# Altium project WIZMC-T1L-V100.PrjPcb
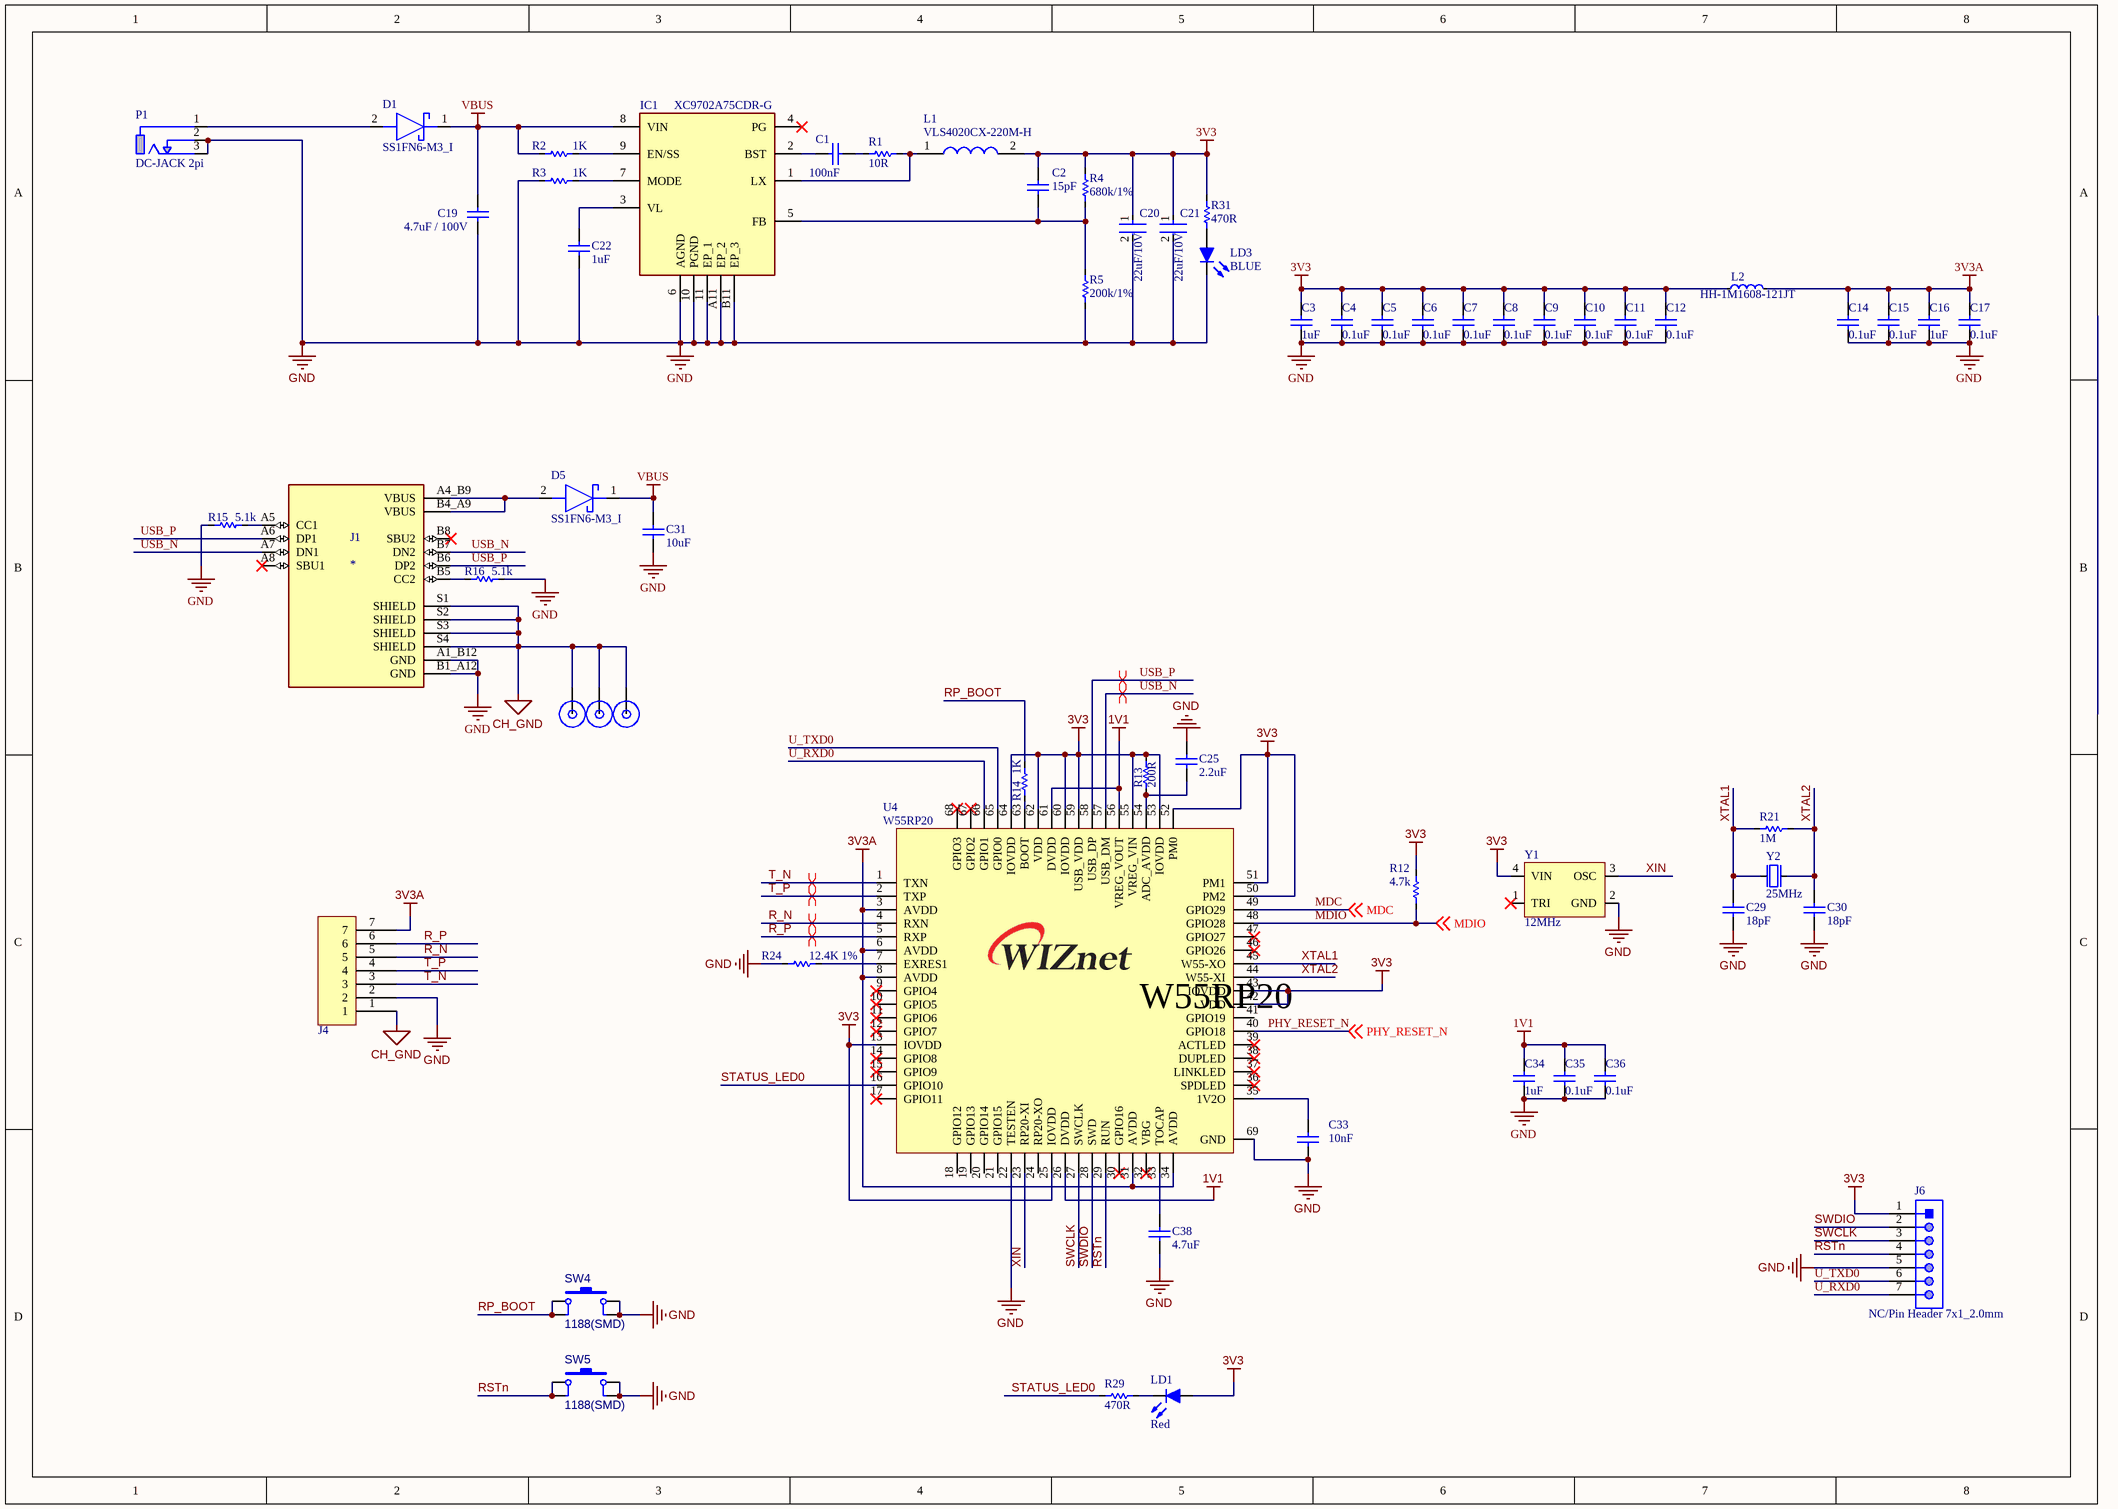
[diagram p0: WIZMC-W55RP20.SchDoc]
3 sheets, 133 parts. Net scope: flat (ports and power ports of the same name join across sheets).
Board file: WIZMC-T1L-V100.PcbDoc
Sheets:
  WIZMC-W55RP20.SchDoc
  WIZMC-ADIN1100.SchDoc
  WIZMC-ADIN1200.SchDoc

## Sheet WIZMC-W55RP20.SchDoc
size A3; SheetNumber: 1; SheetTotal: 3

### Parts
C1  100nF  [CAP-0402]
C2  15pF  [CAP-0402]
C3  1uF  [CAP-0402]
C4  0.1uF  [CAP-0402]
C5  0.1uF  [CAP-0402]
C6  0.1uF  [CAP-0402]
C7  0.1uF  [CAP-0402]
C8  0.1uF  [CAP-0402]
C9  0.1uF  [CAP-0402]
C10  0.1uF  [CAP-0402]
C11  0.1uF  [CAP-0402]
C12  0.1uF  [CAP-0402]
C14  0.1uF  [CAP-0402]
C15  0.1uF  [CAP-0402]
C16  1uF  [CAP-0402]
C17  0.1uF  [CAP-0402]
C19  4.7uF / 100V  [CAP-1210]
C20  22uF/10V  [CAP-1206]
C21  22uF/10V  [CAP-1206]
C22  1uF  [CAP-0603]
C25  2.2uF  [CAP-0603]
C29  18pF  [CAP-0402]
C30  18pF  [CAP-0402]
C31  10uF  [CAP-0805]
C33  10nF  [CAP-0402]
C34  1uF  [CAP-0402]
C35  0.1uF  [CAP-0402]
C36  0.1uF  [CAP-0402]
C38  4.7uF  [CAP-0603]
D1  SS1FN6-M3_I  [SODFL3718X108N]
D5  SS1FN6-M3_I  [SODFL3718X108N]
H1  PCB Hole  [M3_HOLE]  (value not drawn)  (no BOM)
H2  PCB Hole  [M3_HOLE]  (value not drawn)  (no BOM)
H4  PCB Hole  [M3_HOLE]  (value not drawn)  (no BOM)
IC1  XC9702A75CDR-G  [XC9135B18CDRG]
J1  *  [USB-C]
J4  2.54mm 1x9 Pin Header DIP  [Pin-Header(DIP)_7x1_2.0mm]  (value not drawn)
J6  NC/Pin Header 7x1_2.0mm  [Pin-Header(DIP)_7x1_2.0mm]
L1  VLS4020CX-220M-H  [XAL40XX]
L2  HH-1M1608-121JT  [IND-0603]
LD1  Red  [LED-0603-RED]
LD3  BLUE  [LED-0603-RED]
P1  DC-JACK 2pi  [DC-JACK 2pi]
R1  10R  [RES-0402]
R2  1K  [RES-0402]
R3  1K  [RES-0402]
R4  680k/1%  [RES-0402]
R5  200k/1%  [RES-0402]
R12  4.7k  [RES-0402]
R13  200R  [RES-0402]
R14  1K  [RES-0402]
R15  5.1k  [RES-0402]
R16  5.1k  [RES-0402]
R21  1M  [RES-0402]
R24  12.4K 1%  [RES-0402]
R29  470R  [RES-0402]
R31  470R  [RES-0402]
SW4  1188(SMD)  [1188]
SW5  1188(SMD)  [1188]
U4  W55RP20  [QFN68]
Y1  12MHz  [3225_XTAL]
Y2  25MHz  [OSC-82J0626]

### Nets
1V1: C34.2 C35.2 C36.2 U4.26(DVDD) U4.56(VREG_VOUT) U4.61(DVDD)
3V3: C2.2 C3.2 C4.2 C5.2 C6.2 C7.2 C8.2 C9.2 C10.2 C11.2 C12.2 C20.1 C21.1 J6.1 L1.2 L2.1 LD1.1(A) R4.2 R12.2 R13.2 R31.1 U4.13(IOVDD) U4.25(IOVDD) U4.42(VDD) U4.43(IOVDD) U4.50(PM2) U4.51(PM1) U4.52(PM0) U4.53(IOVDD) U4.55(VREG_VIN) U4.59(USB_VDD) U4.60(IOVDD) U4.62(VDD) U4.64(IOVDD) Y1.4(VIN)
3V3A: C14.2 C15.2 C16.2 C17.2 J4.7 L2.2 U4.3(AVDD) U4.6(AVDD) U4.8(AVDD) U4.31(AVDD) U4.34(AVDD)
CH_GND: H1.1 H2.1 H4.1 J1.S1(SHIELD) J1.S2(SHIELD) J1.S3(SHIELD) J1.S4(SHIELD) J4.1
GND: C3.1 C4.1 C5.1 C6.1 C7.1 C8.1 C9.1 C10.1 C11.1 C12.1 C14.1 C15.1 C16.1 C17.1 C19.1 C20.2 C21.2 C22.1 C25.1 C29.1 C30.1 C31.1 C33.1 C34.1 C35.1 C36.1 C38.1 IC1.6(AGND) IC1.10(PGND) IC1.11(EP_1) IC1.A11(EP_2) IC1.B11(EP_3) J1.A1_B12(GND) J1.B1_A12(GND) J4.2 J6.5 LD3.2(K) P1.2(GND) P1.3(GND) R3.1 R5.1 R15.2 R16.1 R24.1 SW4.1 SW4.2 SW5.1 SW5.2 U4.22(TESTEN) U4.69(GND) Y1.2(GND) Y2.2(GND) Y2.4(GND)
VBUS: C19.2 C31.2 D1.1(K) D5.1(K) IC1.8(VIN) R2.1
MDC: U4.49(GPIO29) ; off-sheet MDC
MDIO: R12.1 U4.48(GPIO28) ; off-sheet MDIO
PHY_RESET_N: U4.40(GPIO18) ; off-sheet PHY_RESET_N
R_N: J4.5 U4.4(RXN)
R_P: J4.6 U4.5(RXP)
RP_BOOT: R14.2 SW4.3 SW4.4
RSTn: J6.4 SW5.3 SW5.4 U4.29(RUN)
STATUS_LED0: R29.1 U4.16(GPIO10)
SWCLK: J6.3 U4.27(SWCLK)
SWDIO: J6.2 U4.28(SWD)
T_N: J4.3 U4.1(TXN)
T_P: J4.4 U4.2(TXP)
U_RXD0: J6.7 U4.66(GPIO1)
U_TXD0: J6.6 U4.65(GPIO0)
USB_N: J1.A7(DN1) J1.B7(DN2) U4.57(USB_DM)
USB_P: J1.A6(DP1) J1.B6(DP2) U4.58(USB_DP)
XIN: U4.23(RP20-XI) Y1.3(OSC)
XTAL1: C29.2 R21.1 U4.45(W55-XO) Y2.1(inp)
XTAL2: C30.2 R21.2 U4.44(W55-XI) Y2.3(out)
NetC1_1: C1.1 R1.1
NetC1_2: C1.2 IC1.2(BST)
NetC2_1: C2.1 IC1.5(FB) R4.1 R5.2
NetC22_2: C22.2 IC1.3(VL)
NetC25_2: C25.2 R13.1 U4.54(ADC_AVDD)
NetC33_2: C33.2 U4.35(1V2O)
NetC38_2: C38.2 U4.33(TOCAP)
NetD1_2: D1.2(A) P1.1(VCC)
NetD5_2: D5.2(A) J1.A4_B9(VBUS) J1.B4_A9(VBUS)
NetIC1_1: IC1.1(LX) L1.1 R1.2
NetIC1_7: IC1.7(MODE) R3.2
NetIC1_9: IC1.9(EN/SS) R2.2
NetJ1_A5: J1.A5(CC1) R15.1
NetJ1_B5: J1.B5(CC2) R16.2
NetLD1_2: LD1.2(K) R29.2
NetLD3_1: LD3.1(A) R31.2
NetR14_1: R14.1 U4.63(BOOT)
NetR24_2: R24.2 U4.7(EXRES1)

Not connected (* = marked no-connect by the designer): IC1 4(PG)*; J1 A8(SBU1)* B8(SBU2)*; U4 9(GPIO4)* 10(GPIO5)* 11(GPIO6)* 12(GPIO7)* 14(GPIO8)* 15(GPIO9)* 17(GPIO11)* 18(GPIO12) 19(GPIO13) 20(GPIO14) 21(GPIO15) 24(RP20-XO) 30(GPIO16)* 32(VBG)* 36(SPDLED)* 37(LINKLED)* 38(DUPLED)* 39(ACTLED)* 41(GPIO19) 46(GPIO26)* 47(GPIO27)* 67(GPIO2)* 68(GPIO3)*; Y1 1(TRI)*

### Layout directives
differential pair: R_N, R_P, T_N, T_P, USB_N, USB_P

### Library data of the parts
C1 C2 C25 C29 C30 C33 = CAP-0402: MLCC-0402(1005)
C3-C12 C14-C17 C34-C36 = CAP-0402: Ceramic CAP 0402(1005)
C19 = CAP-1210: MLCC-1210(3225)
C20 C21 = CAP-1206: MLCC-1206(3216); Manufacturer: KEMET; Manufacturer Part Number: C1206X102KGRACTU; Tolerance: 10%; Voltage Rating (DC): 2kV; Capacitance: 1nF; Dielectric: X7R; Dielectric Material: Ceramic
C22 C38 = CAP-0603: MLCC-0603(1608)
C31 = CAP-0805: MLCC-0805(2012)
D1 D5 = SS1FN6-M3_I: Schottky Diode; Manufacturer_Name: Vishay; Manufacturer_Part_Number: SS1FN6-M3/I
H1 H2 H4 = PCB Hole: PCB Supporter Hole
IC1 = XC9702A75CDR-G: Integrated Circuit; Manufacturer_Name: Torex
J1 = TYPE-C-31-M-12: USB Connectors 24 Receptacle 1 8.94*7.3mm RoHS; MF: HRO Electronics Co., Ltd.
J4 = 2.54mm 1x7 Pin Header
J6 = Pin Header 7x1_2.0mm: Connector; Manufacturer_Name: Harwin; Manufacturer_Part_Number: M22-2010705
L1 = XAL4040-822MEC: Inductor; Manufacturer_Name: COILCRAFT
L2 = IND-0603: Inductor 0603(1608)
LD1 LD3 = LED-0603
R1-R5 R12-R14 R21 R24 = RES-0402: Chip Resistor 0402(1005)
R15 R16 R29 R31 = RES-0402
SW4 SW5 = 1188(SMD): SMD TACT SWITCH
U4 = W55RP20: WIZnet Hardwired TCP/IP Chip
Y1 = OSC-3225: OSC 25MHz,3.2x2.5 SMD
Y2 = OSC-82J0626-25MHz: X-tal 25MHz,3.2x2.5 SMD, CL=18pF

## Sheet WIZMC-ADIN1100.SchDoc: WIZMD-SPE
size A4; Date: 2025-08-18; DocumentNumber: 2; Revision: 0.1; SheetNumber: 2; SheetTotal: 3
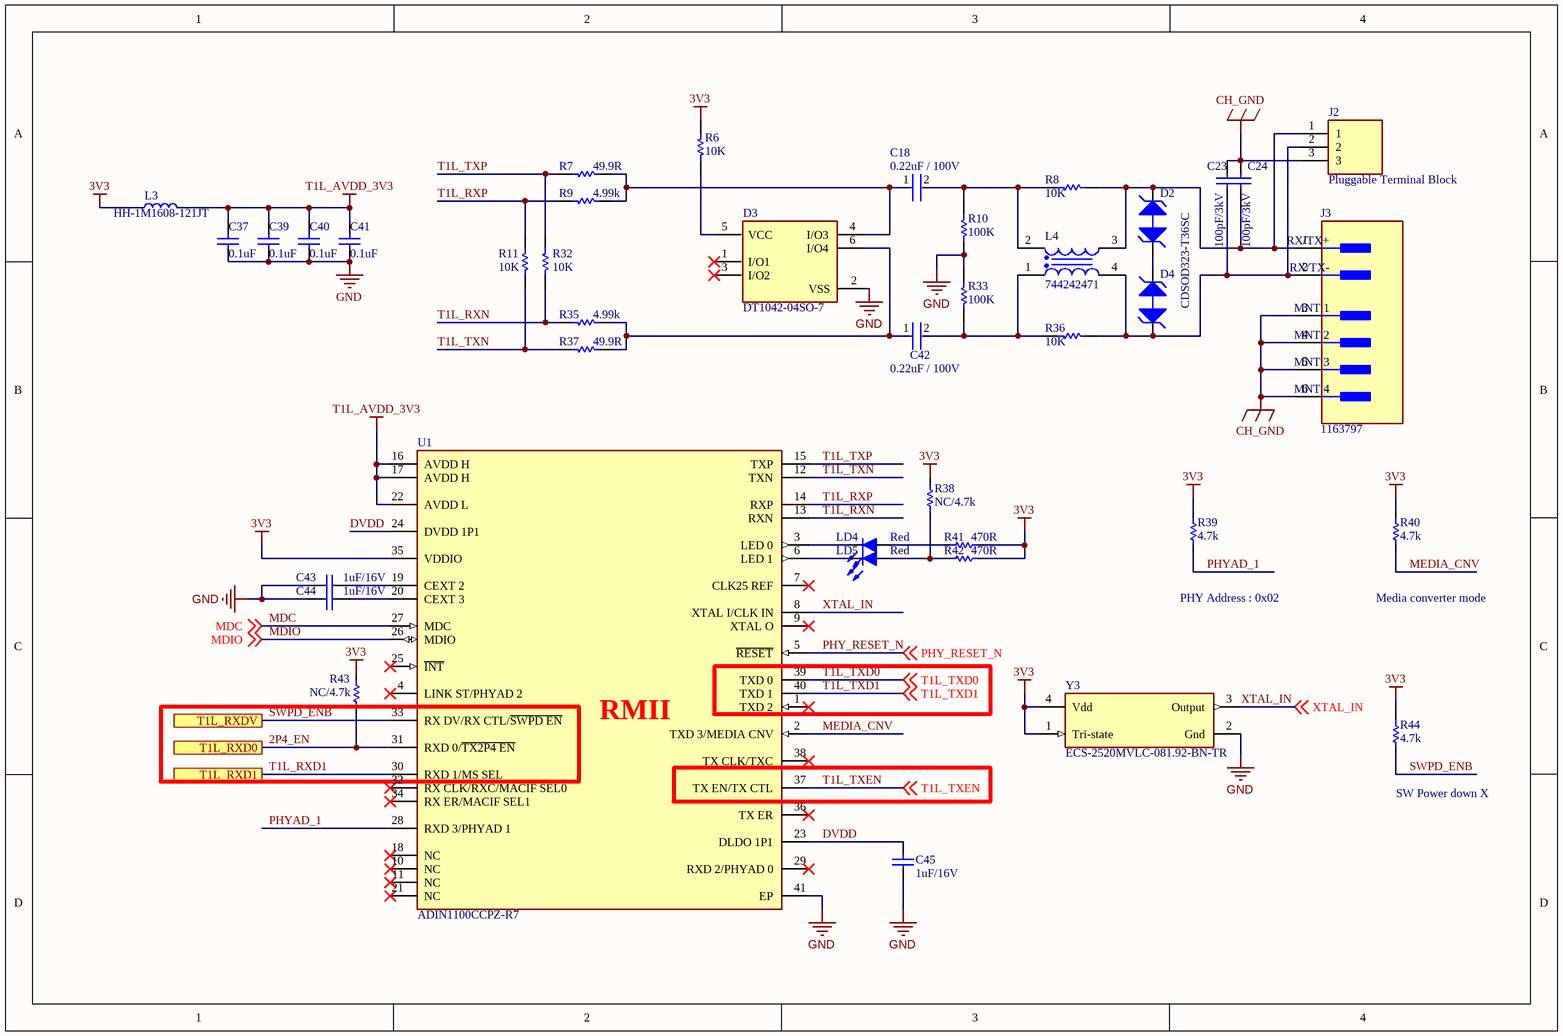
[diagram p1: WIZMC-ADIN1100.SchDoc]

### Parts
C18  0.22uF / 100V  [CAP-1206]
C23  100pF/3kV  [CAP-1808]
C24  100pF/3kV  [CAP-1808]
C37  0.1uF  [CAP-0402]
C39  0.1uF  [CAP-0402]
C40  0.1uF  [CAP-0402]
C41  0.1uF  [CAP-0402]
C42  0.22uF / 100V  [CAP-1206]
C43  1uF/16V  [CAP-0603]
C44  1uF/16V  [CAP-0603]
C45  1uF/16V  [CAP-0603]
D2  CDSOD323-T36SC  [SOD-323(1-C,2-A)]  (value not drawn)
D3  DT1042-04SO-7  [FP-SOT26_SC74R-MFG]
D4  CDSOD323-T36SC  [SOD-323(1-C,2-A)]
J2  Pluggable Terminal Block  [1803280]
J3  1163797  [FP-1163797-MFG]
L3  HH-1M1608-121JT  [IND-0603]
L4  744242471  [WE-SLM_L6W3.3H3.3]
LD4  Red  [LED-0603-RED]
LD5  Red  [LED-0603-RED]
R6  10K  [RES-0603]
R7  49.9R  [RES-0603]
R8  10K  [RES-0603]
R9  4.99k  [RES-0603]
R10  100K  [RES-0603]
R11  10K  [RES-0603]
R32  10K  [RES-0603]
R33  100K  [RES-0603]
R35  4.99k  [RES-0603]
R36  10K  [RES-0603]
R37  49.9R  [RES-0603]
R38  NC/4.7k  [RES-0402]
R39  4.7k  [RES-0402]
R40  4.7k  [RES-0402]
R41  470R  [RES-0402]
R42  470R  [RES-0402]
R43  NC/4.7k  [RES-0402]
R44  4.7k  [RES-0402]
U1  ADIN1100CCPZ-R7  [FP-CP-40-29-IPC_C]
Y3  ECS-2520MVLC-081.92-BN-TR  [FP-ECS-2520MVLC-MFG]

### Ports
T1L_RXD0, T1L_RXD1, T1L_RXDV

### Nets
3V3: L3.1 R6.1 R38.2 R39.2 R40.2 R41.2 R42.2 R43.2 R44.2 U1.35(VDDIO) Y3.1(Tri-state) Y3.4(Vdd)
CH_GND: C23.1 C24.1 J2.3 J3.3(MNT_1) J3.4(MNT_2) J3.5(MNT_3) J3.6(MNT_4)
GND: C37.1 C39.1 C40.1 C41.1 C43.2 C44.2 C45.1 D3.2(VSS) R10.2 R33.1 U1.41(EP) Y3.2(Gnd)
T1L_AVDD_3V3: C37.2 C39.2 C40.2 C41.2 L3.2 U1.16(AVDD_H) U1.17(AVDD_H) U1.22(AVDD_L)
2P4_EN: R43.1 U1.31(RXD_0/~{TX2P4_EN}) ; port T1L_RXD0
DVDD: C45.2 U1.23(DLDO_1P1) U1.24(DVDD_1P1)
MDC: U1.27(MDC) ; off-sheet MDC
MDIO: U1.26(MDIO) ; off-sheet MDIO
MEDIA_CNV: R40.1 U1.2(TXD_3/MEDIA_CNV)
PHY_RESET_N: U1.5(~{RESET}) ; off-sheet PHY_RESET_N
PHYAD_1: R39.1 U1.28(RXD_3/PHYAD_1)
SWPD_ENB: R44.1 U1.33(RX_DV/RX_CTL/~{SWPD_EN}) ; port T1L_RXDV
T1L_RXD1: U1.30(RXD_1/MS_SEL) ; port T1L_RXD1
T1L_RXN: R32.1 R35.1 U1.13(RXN)
T1L_RXP: R9.1 R11.2 U1.14(RXP)
T1L_TXD0: U1.39(TXD_0) ; off-sheet T1L_TXD0
T1L_TXD1: U1.40(TXD_1) ; off-sheet T1L_TXD1
T1L_TXEN: U1.37(TX_EN/TX_CTL) ; off-sheet T1L_TXEN  [project net E_MACIF_SEL1]
T1L_TXN: R11.1 R37.1 U1.12(TXN)
T1L_TXP: R7.1 R32.2 U1.15(TXP)
XTAL_IN: U1.8(XTAL_I/CLK_IN) Y3.3(Output) ; off-sheet XTAL_IN
NetC18_1: C18.1 D3.4(I/O3) R7.2 R9.2
NetC18_2: C18.2 L4.2 R8.2 R10.1
NetC23_2: C23.2 D4.1(A1) J2.2 J3.2(RX/TX-) L4.4 R36.1
NetC24_2: C24.2 D2.2(A2) J2.1 J3.1(RX/TX+) L4.3 R8.1
NetC42_1: C42.1 D3.6(I/O4) R35.2 R37.2
NetC42_2: C42.2 L4.1 R33.2 R36.2
NetC43_1: C43.1 U1.19(CEXT_2)
NetC44_1: C44.1 U1.20(CEXT_3)
NetD2_1: D2.1(A1) D4.2(A2)
NetD3_5: D3.5(VCC) R6.2
NetLD4_1: LD4.1(A) R41.1
NetLD4_2: LD4.2(K) U1.3(LED_0)
NetLD5_1: LD5.1(A) R38.1 R42.1
NetLD5_2: LD5.2(K) U1.6(LED_1)

Not connected (* = marked no-connect by the designer): D3 1(I/O1)* 3(I/O2)*; U1 1(TXD_2)* 4(LINK_ST/PHYAD_2)* 7(CLK25_REF)* 9(XTAL_O)* 10(NC)* 11(NC)* 18(NC)* 21(NC)* 25(~{INT})* 29(RXD_2/PHYAD_0)* 32(RX_CLK/RXC/MACIF_SEL0)* 34(RX_ER/MACIF_SEL1)* 36(TX_ER)* 38(TX_CLK/TXC)*

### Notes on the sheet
- (near R39) PHY Address : 0x02
- (near R40) Media converter mode
- (near U1) RMII
- (near R44) SW Power down X

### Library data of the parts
C18 C42 = CAP-1206: as C20 on sheet WIZMC-W55RP20
C23 C24 = CAP-1808: Ceramic CAP 1808(4520)
C37 C39-C41 = CAP-0402: Ceramic CAP 0402(1005)
C43-C45 = CAP-0603: MLCC-0603(1608)
D2 D4 = CDSOD323-T36SC: DIODE-TVS (SMB); PartNumber: SMAJ58CA-E3/61; Manufacturer: Vishay Semiconductor; Manufacturer: Vishay Semiconductors; PPPM (W): 400, 300; ID (uA): 2; IFSM: 40 A; VWM (V): 58; VBR Bi-Directional (V): 6.4 to 231; Packing: Tape and Reel
D3 = CMP-12828-000009-1: TVS DIODE 5V 9V SOT26; Manufacturer: Diodes Inc.; Peak Pulse Power: 55W; Value: 0.65pF; Peak Pulse Current: 6A; Clamping Voltage: 6.3V; Number Of Channels: 4; Standoff Height: 0.013mm; Direction: Unidirectional; Breakdown Voltage: 6.2V
J2 = Pluggable Terminal Block: 3Pos_3.81mm_Pluggable_Terminal_Blocks; Manufacturer_Name: Phoenix Contact
J3 = CMP-09401-000002-1: SPE PCB CONNECTOR, TYPE: IEC 631
L3 = IND-0603: Inductor 0603(1608)
L4 = CMP-03913-19122241-1: 744242471 Common Mode Chokes Dual 470uH 2.2kOhm 100kHz 400mA 350mOhm DCR SMD T/R; Voltage Rating: 80V; Inductance: 470µH; DC Resistance (DCR): 350mΩ; Number of Lines: 2; Tolerance: 50%; Impedance: 2.2kΩ
LD4 LD5 = LED-0603
R6-R11 R32 R33 R35-R37 = RES-0603
R38-R44 = RES-0402
U1 = CMP-09095-000007-1: 10BASE-T1L PHY WITH 4 MDI
Y3 = CMP-40224-000048-1: XTAL OSC XO 8.192MHZ CMOS SMD

## Sheet WIZMC-ADIN1200.SchDoc
size A4; SheetNumber: 3; SheetTotal: 3
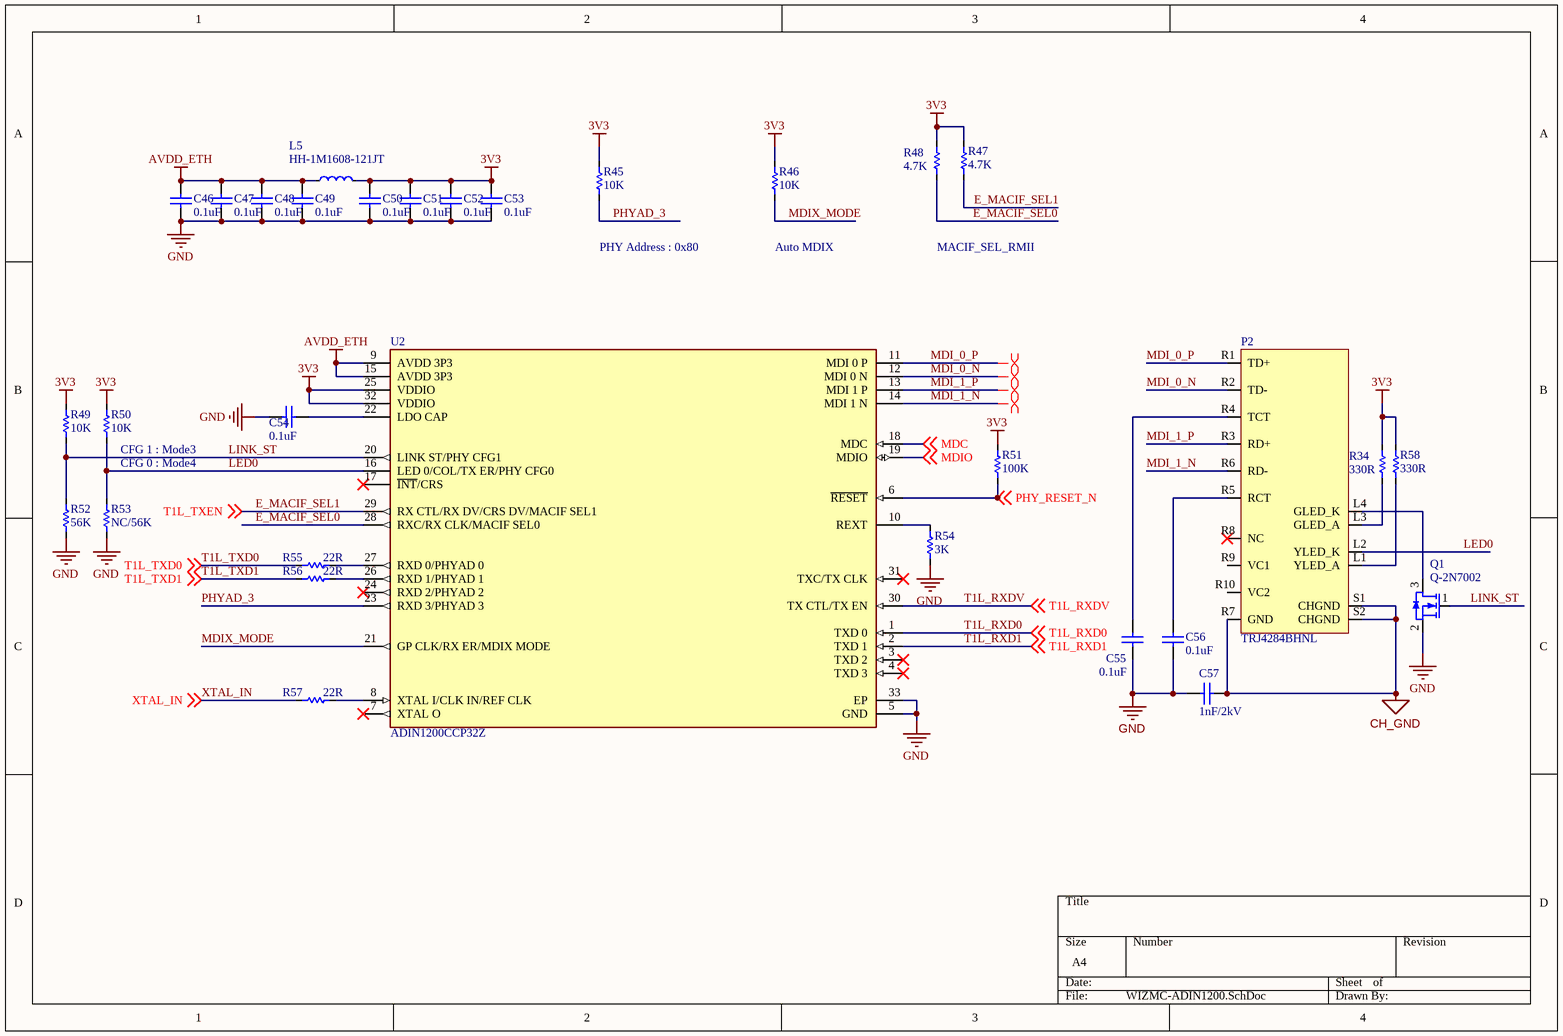
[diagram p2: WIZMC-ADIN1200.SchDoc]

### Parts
C46  0.1uF  [CAP-0402]
C47  0.1uF  [CAP-0402]
C48  0.1uF  [CAP-0402]
C49  0.1uF  [CAP-0402]
C50  0.1uF  [CAP-0402]
C51  0.1uF  [CAP-0402]
C52  0.1uF  [CAP-0402]
C53  0.1uF  [CAP-0402]
C54  0.1uF  [CAP-0402]
C55  0.1uF  [CAP-0402]
C56  0.1uF  [CAP-0402]
C57  1nF/2kV  [CAP-1808]
L5  HH-1M1608-121JT  [IND-0603]
P2  TRJ4284BHNL  [RB1-ZZ-0049]
Q1  Q-2N7002  [SOT23-3L]
R34  330R  [RES-0402]
R45  10K  [RES-0402]
R46  10K  [RES-0402]
R47  4.7K  [RES-0402]
R48  4.7K  [RES-0402]
R49  10K  [RES-0402]
R50  10K  [RES-0402]
R51  100K  [RES-0402]
R52  56K  [RES-0402]
R53  NC/56K  [RES-0402]
R54  3K  [RES-0402]
R55  22R  [RES-0402]
R56  22R  [RES-0402]
R57  22R  [RES-0402]
R58  330R  [RES-0402]
U2  ADIN1200CCP32Z  [FP-CP-32-31-MFG]

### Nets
3V3: C50.2 C51.2 C52.2 C53.2 L5.1 R34.2 R45.2 R46.2 R47.2 R48.2 R49.2 R50.2 R51.1 R58.2 U2.25(VDDIO) U2.32(VDDIO)
AVDD_ETH: C46.2 C47.2 C48.2 C49.2 L5.2 U2.9(AVDD_3P3) U2.15(AVDD_3P3)
CH_GND: C57.2 P2.R7(GND) P2.S1(CHGND) P2.S2(CHGND)
GND: C46.1 C47.1 C48.1 C49.1 C50.1 C51.1 C52.1 C53.1 C54.1 C55.1 C56.1 C57.1 Q1.2(S) R52.1 R53.1 R54.2 U2.5(GND) U2.33(EP)
E_MACIF_SEL0: R48.1 U2.28(RXC/RX_CLK/MACIF_SEL0)
E_MACIF_SEL1: R47.1 U2.29(RX_CTL/RX_DV/CRS_DV/MACIF_SEL1) ; off-sheet T1L_TXEN  [also labelled T1L_TXEN]
LED0: P2.L2(YLED_K) R50.1 R53.2 U2.16(LED_0/COL/TX_ER/PHY_CFG0)
LINK_ST: Q1.1(G) R49.1 R52.2 U2.20(LINK_ST/PHY_CFG1)
MDC: U2.18(MDC) ; off-sheet MDC
MDI_0_N: P2.R2(TD-) U2.12(MDI_0_N)
MDI_0_P: P2.R1(TD+) U2.11(MDI_0_P)
MDI_1_N: P2.R6(RD-) U2.14(MDI_1_N)
MDI_1_P: P2.R3(RD+) U2.13(MDI_1_P)
MDIO: U2.19(MDIO) ; off-sheet MDIO
MDIX_MODE: R46.1 U2.21(GP_CLK/RX_ER/MDIX_MODE)
PHY_RESET_N: R51.2 U2.6(~{RESET}) ; off-sheet PHY_RESET_N
PHYAD_3: R45.1 U2.23(RXD_3/PHYAD_3)
T1L_RXD0: U2.1(TXD_0) ; off-sheet T1L_RXD0
T1L_RXD1: U2.2(TXD_1) ; off-sheet T1L_RXD1
T1L_RXDV: U2.30(TX_CTL/TX_EN) ; off-sheet T1L_RXDV
T1L_TXD0: R55.2 ; off-sheet T1L_TXD0
T1L_TXD1: R56.2 ; off-sheet T1L_TXD1
XTAL_IN: R57.2 ; off-sheet XTAL_IN
NetC54_2: C54.2 U2.22(LDO_CAP)
NetC55_2: C55.2 P2.R4(TCT)
NetC56_2: C56.2 P2.R5(RCT)
NetP2_L1: P2.L1(YLED_A) R58.1
NetP2_L3: P2.L3(GLED_A) R34.1
NetP2_L4: P2.L4(GLED_K) Q1.3(D)
NetR54_1: R54.1 U2.10(REXT)
NetR55_1: R55.1 U2.27(RXD_0/PHYAD_0)
NetR56_1: R56.1 U2.26(RXD_1/PHYAD_1)
NetR57_1: R57.1 U2.8(XTAL_I/CLK_IN/REF_CLK)

Not connected (* = marked no-connect by the designer): P2 R8(NC)* R9(VC1) R10(VC2); U2 3(TXD_2)* 4(TXD_3)* 7(XTAL_O)* 17(~{INT}/CRS)* 24(RXD_2/PHYAD_2)* 31(TXC/TX_CLK)*

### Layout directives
differential pair: MDI_0_N, MDI_0_P, MDI_1_N, MDI_1_P

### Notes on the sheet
- (near R45) PHY Address : 0x80
- (near R46) Auto MDIX
- MACIF_SEL_RMII
- (near R50) CFG 1 : Mode3
- CFG 0 : Mode4

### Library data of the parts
C46-C56 = CAP-0402: Ceramic CAP 0402(1005)
C57 = CAP-1808: MLCC-1808(4520)
L5 = IND-0603: Inductor 0603(1608)
P2 = RB1-ZZ-0049: PoE RJ45
Q1 = Q-2N7002: N-Channel 60-V (D-S) MOSFET
R34 R58 = RES-0402: Chip Resistor 0402(1005)
R45-R57 = RES-0402
U2 = CMP-09095-000001-1: INDUSTRIAL ETHERNET GIGABIT PHY; Manufacturer: Analog Devices; Nominal Supply Current: 20-31mA; Data Rate: 100Mbits/s; Standoff Height: 0.02mm; Max Junction Temp: +125°C; Min Supply Voltage: 1.71V; Simplex Duplex: Full Duplex; Max Supply Voltage: 3.46V; Number Of Channels: 4

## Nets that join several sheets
3V3: WIZMC-W55RP20 (35 pins), WIZMC-ADIN1100 (12 pins), WIZMC-ADIN1200 (16 pins)
CH_GND: WIZMC-W55RP20 (8 pins), WIZMC-ADIN1100 (7 pins), WIZMC-ADIN1200 (C57.2 P2.R7 P2.S1 P2.S2)
GND: WIZMC-W55RP20 (53 pins), WIZMC-ADIN1100 (12 pins), WIZMC-ADIN1200 (18 pins)
E_MACIF_SEL1: WIZMC-ADIN1100 (U1.37), WIZMC-ADIN1200 (R47.1 U2.29)
MDC: WIZMC-W55RP20 (U4.49), WIZMC-ADIN1100 (U1.27), WIZMC-ADIN1200 (U2.18)
MDIO: WIZMC-W55RP20 (R12.1 U4.48), WIZMC-ADIN1100 (U1.26), WIZMC-ADIN1200 (U2.19)
PHY_RESET_N: WIZMC-W55RP20 (U4.40), WIZMC-ADIN1100 (U1.5), WIZMC-ADIN1200 (R51.2 U2.6)
T1L_TXD0: WIZMC-ADIN1100 (U1.39), WIZMC-ADIN1200 (R55.2)
T1L_TXD1: WIZMC-ADIN1100 (U1.40), WIZMC-ADIN1200 (R56.2)
XTAL_IN: WIZMC-ADIN1100 (U1.8 Y3.3), WIZMC-ADIN1200 (R57.2)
